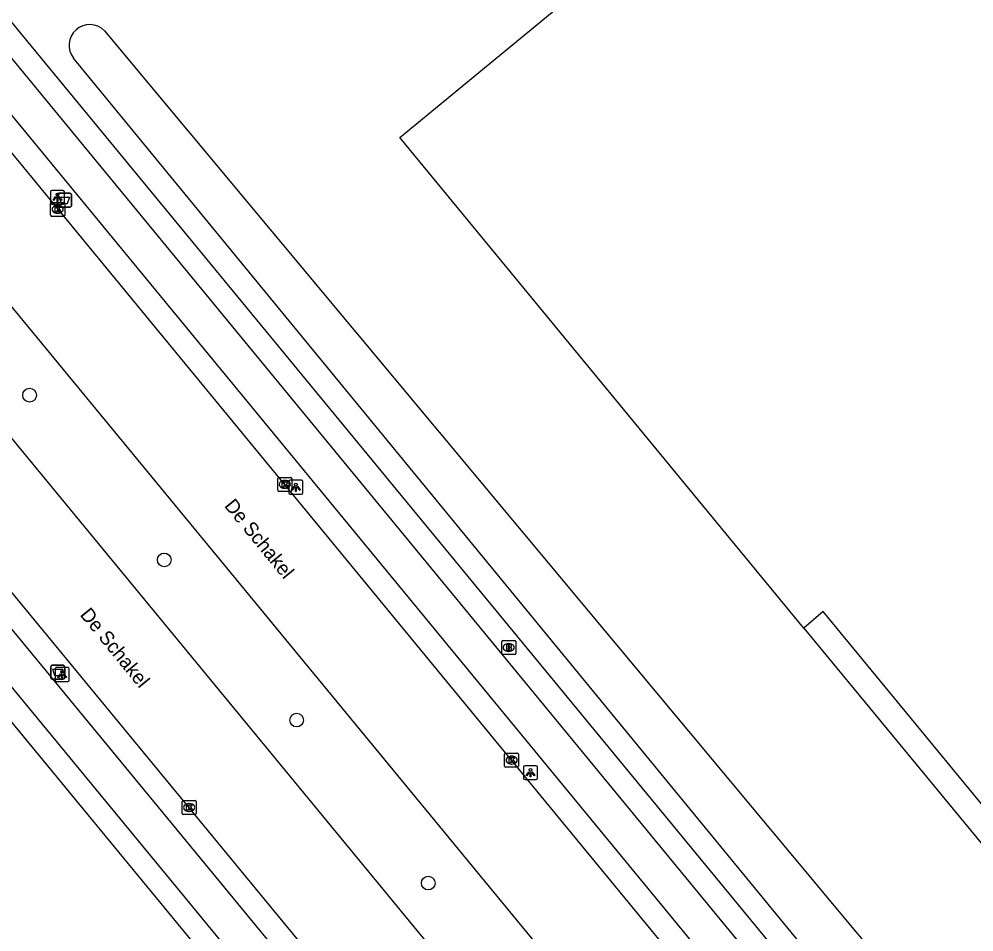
# Model space of a CAD drawing. Extents: x 156141 to 158132, y 385651 to 388399.
# Drawn here: x 157052.6 to 157120.8, y 386413.2 to 386478.5 of the extents above; entities that cross this region are included whole.
import ezdxf

# ---------------------------------------------------------------- set-up
doc = ezdxf.new("R2010")
doc.units = 0
for name, color, linetype in [('IMGEO_Afvalbak', 7, 'Continuous'), ('IMGEO_Boom', 7, 'Continuous'), ('IMGEO_Brandkraan', 7, 'Continuous'), ('IMGEO_Fietspad_gesloten', 7, 'Continuous'), ('IMGEO_Kolk', 7, 'Continuous'), ('IMGEO_Lichtpunt', 7, 'Continuous'), ('IMGEO_Openbare_ruimte_label', 7, 'Continuous'), ('IMGEO_Pand', 7, 'Continuous'), ('IMGEO_Pand_overbouw', 7, 'Continuous'), ('IMGEO_Rijbaan_lokaal_gesloten', 7, 'Continuous'), ('IMGEO_Voetpad_open', 7, 'Continuous'), ('IMGEO_Waterloop', 7, 'Continuous')]:
    doc.layers.add(name, color=color, linetype=linetype)

msp = doc.modelspace()

# ---------------------------------------------------------------- linework, layer by layer
at = {"layer": 'IMGEO_Afvalbak'}
for p, q in [((157055.325, 386465.122), (157055.325, 386465.922)), ((157055.325, 386465.922), (157055.325, 386465.122)), ((157055.425, 386466.022), (157056.215, 386466.022)), ((157056.215, 386466.022), (157055.425, 386466.022)), ((157056.315, 386465.922), (157056.315, 386465.122)), ((157056.315, 386465.122), (157056.315, 386465.922)), ((157056.215, 386465.022), (157055.425, 386465.022)), ((157055.425, 386465.022), (157056.215, 386465.022)), ((157054.85, 386431.38), (157054.85, 386432.18)), ((157054.85, 386432.18), (157054.85, 386431.38)), ((157054.95, 386432.28), (157055.74, 386432.28)), ((157055.74, 386432.28), (157054.95, 386432.28)), ((157055.84, 386432.18), (157055.84, 386431.38)), ((157055.84, 386431.38), (157055.84, 386432.18)), ((157055.74, 386431.28), (157054.95, 386431.28)), ((157054.95, 386431.28), (157055.74, 386431.28))]:
    msp.add_line(p, q, dxfattribs=at)
for points in [[(157055.468, 386465.736), (157056.172, 386465.736), (157056.023, 386465.266), (157055.617, 386465.266), (157055.468, 386465.736)], [(157054.993, 386431.994), (157055.697, 386431.994), (157055.548, 386431.524), (157055.142, 386431.524), (157054.993, 386431.994)]]:
    msp.add_lwpolyline(points, dxfattribs=at)
for centre, start, end in [((157055.425, 386465.922), 90, 180), ((157055.425, 386465.922), 90, 180), ((157056.215, 386465.922), 0, 90), ((157056.215, 386465.922), 360, 90), ((157055.425, 386465.122), 180, 270), ((157055.425, 386465.122), 180, 270), ((157056.215, 386465.122), 270, 0), ((157056.215, 386465.122), 270, 0), ((157054.95, 386432.18), 90, 180), ((157054.95, 386432.18), 90, 180), ((157055.74, 386432.18), 0, 90), ((157055.74, 386432.18), 360, 90), ((157054.95, 386431.38), 180, 270), ((157054.95, 386431.38), 180, 270), ((157055.74, 386431.38), 270, 0), ((157055.74, 386431.38), 270, 0)]:
    msp.add_arc(centre, 0.1, start, end, dxfattribs=at)
at = {"layer": 'IMGEO_Boom'}
for centre in [(157053.326, 386451.588), (157062.955, 386439.808), (157072.415, 386428.358), (157081.82, 386416.71)]:
    msp.add_circle(centre, 0.489, dxfattribs=at)
at = {"layer": 'IMGEO_Brandkraan'}
for p, q in [((157087.068, 386433.128), (157087.068, 386433.98)), ((157087.143, 386434.054), (157087.995, 386434.054)), ((157088.069, 386433.98), (157088.069, 386433.128)), ((157087.579, 386433.274), (157087.554, 386433.274)), ((157087.556, 386433.834), (157087.581, 386433.834)), ((157087.995, 386433.054), (157087.143, 386433.054))]:
    msp.add_line(p, q, dxfattribs=at)
for points in [[(157087.068, 386433.128), (157087.068, 386433.98)], [(157087.143, 386434.054), (157087.995, 386434.054)], [(157088.069, 386433.98), (157088.069, 386433.128)], [(157087.416, 386433.754), (157087.416, 386433.354), (157087.629, 386433.354)], [(157087.647, 386433.754), (157087.416, 386433.754)], [(157087.595, 386433.673), (157087.541, 386433.673), (157087.541, 386433.597)], [(157087.541, 386433.597), (157087.594, 386433.597)], [(157087.603, 386433.521), (157087.541, 386433.521), (157087.541, 386433.44)], [(157087.541, 386433.44), (157087.603, 386433.44)], [(157087.995, 386433.054), (157087.143, 386433.054)]]:
    msp.add_lwpolyline(points, dxfattribs=at)
for centre, radius, start, end in [((157087.145, 386433.978), 0.0765, 91.55205, 178.44795), ((157087.145, 386433.978), 0.0765, 91.55205, 178.44795), ((157087.993, 386433.978), 0.0765, 1.55205, 88.44795), ((157087.993, 386433.978), 0.0765, 1.55205, 88.44795), ((157087.596, 386433.635), 0.0379, 267.82845, 90.93552), ((157087.604, 386433.48), 0.0404, 269.87594, 90.50774), ((157087.635, 386433.605), 0.251, 268.66757, 293.53466), ((157087.651, 386433.609), 0.145, 59.4692, 91.53667), ((157087.676, 386433.656), 0.0922, 285.51372, 58.15012), ((157087.681, 386433.464), 0.105, 301.31148, 78.98903), ((157087.145, 386433.13), 0.0765, 181.55205, 268.44795), ((157087.145, 386433.13), 0.0765, 181.55205, 268.44795), ((157087.993, 386433.13), 0.0765, 271.55205, 358.44795), ((157087.993, 386433.13), 0.0765, 271.55205, 358.44795)]:
    msp.add_arc(centre, radius, start, end, dxfattribs=at)
for centre, major_axis, ratio, start_param, end_param in [((157087.555, 386433.554), (-0.387, 0.002), 0.722429, 4.712389, 7.853982), ((157087.58, 386433.554), (-0.39, 0.002), 0.717154, 1.570796, 4.712389)]:
    msp.add_ellipse(centre, major_axis=major_axis, ratio=ratio, start_param=start_param, end_param=end_param, dxfattribs=at)
at = {"layer": 'IMGEO_Fietspad_gesloten'}
for points in [[(156997.229, 386501.521), (157000, 386498.057), (157086.189, 386393.379)], [(157084.094, 386391.796), (157000, 386493.948), (156995.146, 386499.844)], [(157106.117, 386409.97), (157048.253, 386480.295)], [(157047.712, 386476.837), (157104.914, 386407.314)]]:
    msp.add_lwpolyline(points, dxfattribs=at)
at = {"layer": 'IMGEO_Kolk'}
for p, q in [((157054.835, 386464.445), (157054.835, 386465.297)), ((157054.91, 386465.371), (157055.762, 386465.371)), ((157055.836, 386465.297), (157055.836, 386464.445)), ((157055.346, 386464.591), (157055.321, 386464.591)), ((157055.323, 386465.151), (157055.348, 386465.151)), ((157055.762, 386464.371), (157054.91, 386464.371)), ((157071.066, 386444.786), (157071.066, 386445.638)), ((157071.141, 386445.712), (157071.993, 386445.712)), ((157071.554, 386445.492), (157071.579, 386445.492)), ((157072.067, 386445.638), (157072.067, 386444.786)), ((157071.577, 386444.932), (157071.552, 386444.932)), ((157071.993, 386444.712), (157071.141, 386444.712)), ((157087.277, 386425.076), (157087.277, 386425.928)), ((157087.352, 386426.002), (157088.204, 386426.002)), ((157087.765, 386425.782), (157087.79, 386425.782)), ((157088.278, 386425.928), (157088.278, 386425.076)), ((157088.204, 386425.002), (157087.352, 386425.002)), ((157087.788, 386425.222), (157087.763, 386425.222)), ((157064.232, 386421.685), (157064.232, 386422.537)), ((157064.307, 386422.611), (157065.159, 386422.611)), ((157064.72, 386422.391), (157064.745, 386422.391)), ((157065.233, 386422.537), (157065.233, 386421.685)), ((157065.159, 386421.611), (157064.307, 386421.611)), ((157064.743, 386421.831), (157064.718, 386421.831))]:
    msp.add_line(p, q, dxfattribs=at)
for points in [[(157054.835, 386464.445), (157054.835, 386465.297)], [(157054.91, 386465.371), (157055.762, 386465.371)], [(157055.836, 386465.297), (157055.836, 386464.445)], [(157055.156, 386465.071), (157055.279, 386465.071), (157055.279, 386464.92), (157055.409, 386465.071), (157055.573, 386465.071), (157055.427, 386464.92), (157055.58, 386464.671), (157055.428, 386464.671), (157055.343, 386464.835), (157055.279, 386464.768), (157055.279, 386464.671), (157055.156, 386464.671), (157055.156, 386465.071)], [(157055.762, 386464.371), (157054.91, 386464.371)], [(157071.066, 386444.786), (157071.066, 386445.638)], [(157071.141, 386445.712), (157071.993, 386445.712)], [(157072.067, 386445.638), (157072.067, 386444.786)], [(157071.387, 386445.412), (157071.51, 386445.412), (157071.51, 386445.261), (157071.64, 386445.412), (157071.804, 386445.412), (157071.658, 386445.261), (157071.811, 386445.012), (157071.659, 386445.012), (157071.574, 386445.176), (157071.51, 386445.109), (157071.51, 386445.012), (157071.387, 386445.012), (157071.387, 386445.412)], [(157071.993, 386444.712), (157071.141, 386444.712)], [(157087.277, 386425.076), (157087.277, 386425.928)], [(157087.352, 386426.002), (157088.204, 386426.002)], [(157087.598, 386425.702), (157087.721, 386425.702), (157087.721, 386425.551), (157087.851, 386425.702), (157088.015, 386425.702), (157087.869, 386425.551), (157088.022, 386425.302), (157087.87, 386425.302), (157087.785, 386425.466), (157087.721, 386425.399), (157087.721, 386425.302), (157087.598, 386425.302), (157087.598, 386425.702)], [(157088.278, 386425.928), (157088.278, 386425.076)], [(157088.204, 386425.002), (157087.352, 386425.002)], [(157064.232, 386421.685), (157064.232, 386422.537)], [(157064.307, 386422.611), (157065.159, 386422.611)], [(157064.553, 386422.311), (157064.676, 386422.311), (157064.676, 386422.16), (157064.806, 386422.311), (157064.97, 386422.311), (157064.824, 386422.16), (157064.977, 386421.911), (157064.825, 386421.911), (157064.74, 386422.075), (157064.676, 386422.008), (157064.676, 386421.911), (157064.553, 386421.911), (157064.553, 386422.311)], [(157065.233, 386422.537), (157065.233, 386421.685)], [(157065.159, 386421.611), (157064.307, 386421.611)]]:
    msp.add_lwpolyline(points, dxfattribs=at)
for centre, start, end in [((157054.912, 386465.295), 91.55205, 178.44795), ((157054.912, 386465.295), 91.55205, 178.44795), ((157055.76, 386465.295), 1.55205, 88.44795), ((157055.76, 386465.295), 1.55205, 88.44795), ((157054.912, 386464.447), 181.55205, 268.44795), ((157054.912, 386464.447), 181.55205, 268.44795), ((157055.76, 386464.447), 271.55205, 358.44795), ((157055.76, 386464.447), 271.55205, 358.44795), ((157071.143, 386445.636), 91.55205, 178.44795), ((157071.143, 386445.636), 91.55205, 178.44795), ((157071.991, 386445.636), 1.55205, 88.44795), ((157071.991, 386445.636), 1.55205, 88.44795), ((157071.143, 386444.788), 181.55205, 268.44795), ((157071.143, 386444.788), 181.55205, 268.44795), ((157071.991, 386444.788), 271.55205, 358.44795), ((157071.991, 386444.788), 271.55205, 358.44795), ((157087.354, 386425.926), 91.55205, 178.44795), ((157087.354, 386425.926), 91.55205, 178.44795), ((157088.202, 386425.926), 1.55205, 88.44795), ((157088.202, 386425.926), 1.55205, 88.44795), ((157087.354, 386425.078), 181.55205, 268.44795), ((157087.354, 386425.078), 181.55205, 268.44795), ((157088.202, 386425.078), 271.55205, 358.44795), ((157088.202, 386425.078), 271.55205, 358.44795), ((157064.309, 386422.535), 91.55205, 178.44795), ((157064.309, 386422.535), 91.55205, 178.44795), ((157065.157, 386422.535), 1.55205, 88.44795), ((157065.157, 386422.535), 1.55205, 88.44795), ((157064.309, 386421.687), 181.55205, 268.44795), ((157064.309, 386421.687), 181.55205, 268.44795), ((157065.157, 386421.687), 271.55205, 358.44795), ((157065.157, 386421.687), 271.55205, 358.44795)]:
    msp.add_arc(centre, 0.0765, start, end, dxfattribs=at)
for centre, major_axis, ratio, start_param, end_param in [((157055.322, 386464.871), (-0.387, 0.002), 0.722429, 4.712389, 7.853982), ((157055.347, 386464.871), (-0.39, 0.002), 0.717154, 1.570796, 4.712389), ((157071.553, 386445.212), (-0.387, 0.002), 0.722429, 4.712389, 7.853982), ((157071.578, 386445.212), (-0.39, 0.002), 0.717154, 1.570796, 4.712389), ((157087.764, 386425.502), (-0.387, 0.002), 0.722429, 4.712389, 7.853982), ((157087.789, 386425.502), (-0.39, 0.002), 0.717154, 1.570796, 4.712389), ((157064.719, 386422.111), (-0.387, 0.002), 0.722429, 4.712389, 7.853982), ((157064.744, 386422.111), (-0.39, 0.002), 0.717154, 1.570796, 4.712389)]:
    msp.add_ellipse(centre, major_axis=major_axis, ratio=ratio, start_param=start_param, end_param=end_param, dxfattribs=at)
at = {"layer": 'IMGEO_Lichtpunt'}
for p, q in [((157054.817, 386466.133), (157054.817, 386465.326)), ((157054.817, 386466.133), (157054.817, 386465.326)), ((157055.719, 386466.228), (157054.911, 386466.228)), ((157055.719, 386466.228), (157054.911, 386466.228)), ((157055.813, 386465.326), (157055.813, 386466.133)), ((157055.813, 386465.326), (157055.813, 386466.133)), ((157054.911, 386465.232), (157055.719, 386465.232)), ((157054.911, 386465.232), (157055.719, 386465.232)), ((157072.761, 386445.507), (157071.953, 386445.507)), ((157072.761, 386445.507), (157071.953, 386445.507)), ((157071.859, 386445.412), (157071.859, 386444.605)), ((157071.859, 386445.412), (157071.859, 386444.605)), ((157072.855, 386444.605), (157072.855, 386445.412)), ((157072.855, 386444.605), (157072.855, 386445.412)), ((157071.953, 386444.511), (157072.761, 386444.511)), ((157071.953, 386444.511), (157072.761, 386444.511)), ((157055.162, 386432.015), (157055.162, 386431.208)), ((157055.162, 386432.015), (157055.162, 386431.208)), ((157056.064, 386432.11), (157055.256, 386432.11)), ((157056.064, 386432.11), (157055.256, 386432.11)), ((157056.158, 386431.208), (157056.158, 386432.015)), ((157056.158, 386431.208), (157056.158, 386432.015)), ((157055.256, 386431.114), (157056.064, 386431.114)), ((157055.256, 386431.114), (157056.064, 386431.114)), ((157088.628, 386425.007), (157088.628, 386424.2)), ((157088.628, 386425.007), (157088.628, 386424.2)), ((157089.53, 386425.102), (157088.722, 386425.102)), ((157089.53, 386425.102), (157088.722, 386425.102)), ((157089.624, 386424.2), (157089.624, 386425.007)), ((157089.624, 386424.2), (157089.624, 386425.007)), ((157088.722, 386424.106), (157089.53, 386424.106)), ((157088.722, 386424.106), (157089.53, 386424.106))]:
    msp.add_line(p, q, dxfattribs=at)
for points in [[(157055.191, 386465.797), (157055.23, 386465.769), (157055.042, 386465.507), (157055.004, 386465.534), (157055.191, 386465.797)], [(157055.293, 386465.749), (157055.34, 386465.749), (157055.34, 386465.427), (157055.293, 386465.427), (157055.293, 386465.749)], [(157055.403, 386465.769), (157055.441, 386465.796), (157055.628, 386465.534), (157055.589, 386465.506), (157055.403, 386465.769)], [(157072.233, 386445.076), (157072.272, 386445.048), (157072.084, 386444.786), (157072.046, 386444.813), (157072.233, 386445.076)], [(157072.335, 386445.028), (157072.382, 386445.028), (157072.382, 386444.706), (157072.335, 386444.706), (157072.335, 386445.028)], [(157072.445, 386445.048), (157072.483, 386445.075), (157072.67, 386444.813), (157072.631, 386444.785), (157072.445, 386445.048)], [(157055.536, 386431.679), (157055.575, 386431.651), (157055.387, 386431.389), (157055.349, 386431.416), (157055.536, 386431.679)], [(157055.638, 386431.631), (157055.685, 386431.631), (157055.685, 386431.309), (157055.638, 386431.309), (157055.638, 386431.631)], [(157055.748, 386431.651), (157055.786, 386431.678), (157055.973, 386431.416), (157055.934, 386431.388), (157055.748, 386431.651)], [(157089.002, 386424.671), (157089.041, 386424.643), (157088.853, 386424.381), (157088.815, 386424.408), (157089.002, 386424.671)], [(157089.104, 386424.623), (157089.151, 386424.623), (157089.151, 386424.301), (157089.104, 386424.301), (157089.104, 386424.623)], [(157089.214, 386424.643), (157089.252, 386424.67), (157089.439, 386424.408), (157089.4, 386424.38), (157089.214, 386424.643)]]:
    msp.add_lwpolyline(points, dxfattribs=at)
for centre in [(157055.316, 386465.931), (157072.358, 386445.21), (157055.661, 386431.813), (157089.127, 386424.805)]:
    msp.add_circle(centre, 0.0994, dxfattribs=at)
for centre, start, end in [((157054.911, 386466.133), 90, 180), ((157054.911, 386466.133), 90, 180), ((157055.719, 386466.133), 0, 90), ((157055.719, 386466.133), 0, 90), ((157054.911, 386465.326), 180, 270), ((157054.911, 386465.326), 180, 270), ((157055.719, 386465.326), 270, 0), ((157055.719, 386465.326), 270, 360), ((157071.953, 386445.412), 90, 180), ((157071.953, 386445.412), 90, 180), ((157072.761, 386445.412), 0, 90), ((157072.761, 386445.412), 0, 90), ((157071.953, 386444.605), 180, 270), ((157071.953, 386444.605), 180, 270), ((157072.761, 386444.605), 270, 0), ((157072.761, 386444.605), 270, 360), ((157055.256, 386432.015), 90, 180), ((157055.256, 386432.015), 90, 180), ((157056.064, 386432.015), 0, 90), ((157056.064, 386432.015), 0, 90), ((157055.256, 386431.208), 180, 270), ((157055.256, 386431.208), 180, 270), ((157056.064, 386431.208), 270, 0), ((157056.064, 386431.208), 270, 360), ((157088.722, 386425.007), 90, 180), ((157088.722, 386425.007), 90, 180), ((157089.53, 386425.007), 0, 90), ((157089.53, 386425.007), 0, 90), ((157088.722, 386424.2), 180, 270), ((157088.722, 386424.2), 180, 270), ((157089.53, 386424.2), 270, 0), ((157089.53, 386424.2), 270, 360)]:
    msp.add_arc(centre, 0.0946, start, end, dxfattribs=at)
at = {"layer": 'IMGEO_Pand'}
msp.add_lwpolyline([(157116.212, 386500), (157127.098, 386508.962), (157133.365, 386514.121), (157165.777, 386540.804), (157199.375, 386500), (157212.507, 386484.051), (157183.012, 386459.796), (157181.862, 386461.196), (157166.855, 386448.839), (157138.856, 386425.768), (157126.754, 386415.792), (157110.039, 386436.118), (157108.665, 386434.944), (157079.786, 386470.013), (157116.212, 386500)], dxfattribs=at)
at = {"layer": 'IMGEO_Pand_overbouw'}
msp.add_lwpolyline([(157108.665, 386434.944), (157126.515, 386413.267), (157139.993, 386424.367), (157141.385, 386422.655), (157141.518, 386422.764), (157169.359, 386445.693), (157168.245, 386447.074), (157167.989, 386447.391), (157183.012, 386459.796), (157181.862, 386461.196), (157166.855, 386448.839), (157138.856, 386425.768), (157126.754, 386415.792), (157110.039, 386436.118)], close=True, dxfattribs=at)
at = {"layer": 'IMGEO_Rijbaan_lokaal_gesloten'}
for points in [[(157109.728, 386387.854), (157107.759, 386390.255), (157017.392, 386500), (157006.877, 386512.769)], [(157002.333, 386508.861), (157009.629, 386500), (157103.143, 386386.435), (157105.1, 386384.051)], [(157099.714, 386379.637), (157000.586, 386500), (157000, 386500.712), (156999.306, 386501.555)], [(157115.109, 386392.268), (157046.395, 386475.769)]]:
    msp.add_lwpolyline(points, dxfattribs=at)
at = {"layer": 'IMGEO_Voetpad_open'}
for points in [[(156993.904, 386498.844), (157000, 386491.438), (157082.674, 386390.997)], [(157049.528, 386481.275), (157107.842, 386410.438)]]:
    msp.add_lwpolyline(points, dxfattribs=at)
at = {"layer": 'IMGEO_Waterloop'}
for points in [[(157058.683, 386477.643), (157112.372, 386413.22)], [(157108.302, 386412.53), (157056.469, 386475.667)]]:
    msp.add_lwpolyline(points, dxfattribs=at)
for centre, radius, start, end in [((157057.637, 386476.587), 1.487, 45.27143, 218.22653), ((157145.084, 386441.383), 43.165, 220.72727, 233.84935)]:
    msp.add_arc(centre, radius, start, end, dxfattribs=at)

# ---------------------------------------------------------------- texts
at = {"layer": 'IMGEO_Openbare_ruimte_label'}
for p in [(157067.201, 386443.665), (157056.885, 386435.878)]:
    msp.add_text('De Schakel', height=1, rotation=309.19669, dxfattribs=at).set_placement(p)

doc.saveas('drawing.dxf')
